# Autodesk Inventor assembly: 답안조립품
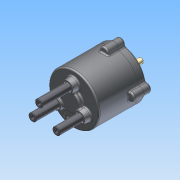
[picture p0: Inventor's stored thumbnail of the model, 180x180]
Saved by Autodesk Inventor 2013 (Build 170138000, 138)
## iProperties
Created: 2014-12
Part Number: 답안조립품
Document SubType Name: Assembly
Designer: Administrator
Mass: 2160.23 g
Surface Area: 1801.17 cm^2
Volume: 438.521 cm^3
Density: 4.92617 g/cm^3
Author: Administrator
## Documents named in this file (14)
- C:\Users\Administrator\Desktop\1급\Inventor1급\답안조립품.iam
- C:\Users\Administrator\Desktop\1급\Inventor1급\몸체.ipt
- C:\Users\Administrator\Desktop\1급\Inventor1급\M5x0.5x20.ipt
- C:\Users\Administrator\Desktop\1급\Inventor1급\가변스프링.ipt
- C:\Users\Administrator\Desktop\1급\Inventor1급\가변스프링2.ipt
- C:\Users\Administrator\Desktop\1급\Inventor1급\가변스프링3.ipt
- C:\Users\Administrator\Desktop\1급\Inventor1급\멈춤링 10 x 1.ipt
- C:\Users\Administrator\Desktop\1급\Inventor1급\멈춤링 22 x 1.2.ipt
- C:\Users\Administrator\Desktop\1급\Inventor1급\메인 축.ipt
- C:\Users\Administrator\Desktop\1급\Inventor1급\베어링 NA 4900.ipt
- C:\Users\Administrator\Desktop\1급\Inventor1급\슬라이드 축.ipt
- C:\Users\Administrator\Desktop\1급\Inventor1급\오일실.ipt
- C:\Users\Administrator\Desktop\1급\Inventor1급\커버.ipt
- C:\Users\Administrator\Desktop\1급\Inventor1급\판캠.ipt
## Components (7 placed, 4 different names)
1. 가변스프링:1
2. 가변스프링2:1
3. 가변스프링3:1
4. M5x0.5x20:1
5. M5x0.5x20:2
6. M5x0.5x20:3
7. M5x0.5x20:4
